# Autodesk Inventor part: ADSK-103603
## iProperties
Created: 2001-01
Part Number: ADSK-103603
Description: Hexagon Socket Head Cap Screw
Document SubType Name: Modeling
Standard: ANSI B18.3 - 3/8 - 16 - 1 1/2
Designer: gao
Density: 1 g/cm^3
Control State: 0
Master: False
Checked Out: False
Shininess: 0.0
Density: 0.0
Volumn: 0.0
Area: 0.0
PropertySet Name: Model Information
Author: gao
